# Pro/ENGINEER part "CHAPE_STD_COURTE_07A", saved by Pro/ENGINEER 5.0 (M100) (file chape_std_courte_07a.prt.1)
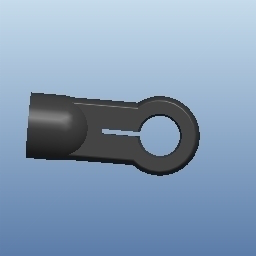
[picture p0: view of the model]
Units: millimeter Newton Second (mmNs); MM, TONNE, HOURS
Materials in the file: NYLON

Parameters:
  PTC_MATERIAL_NAME = "NYLON"

Other named items: DROITE, DESSUS, FACE, CHAPE_STD_COURTE_07

Layers: 02_POINTS, 03_PLANS, 05_SURFACES, 06_REPERES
